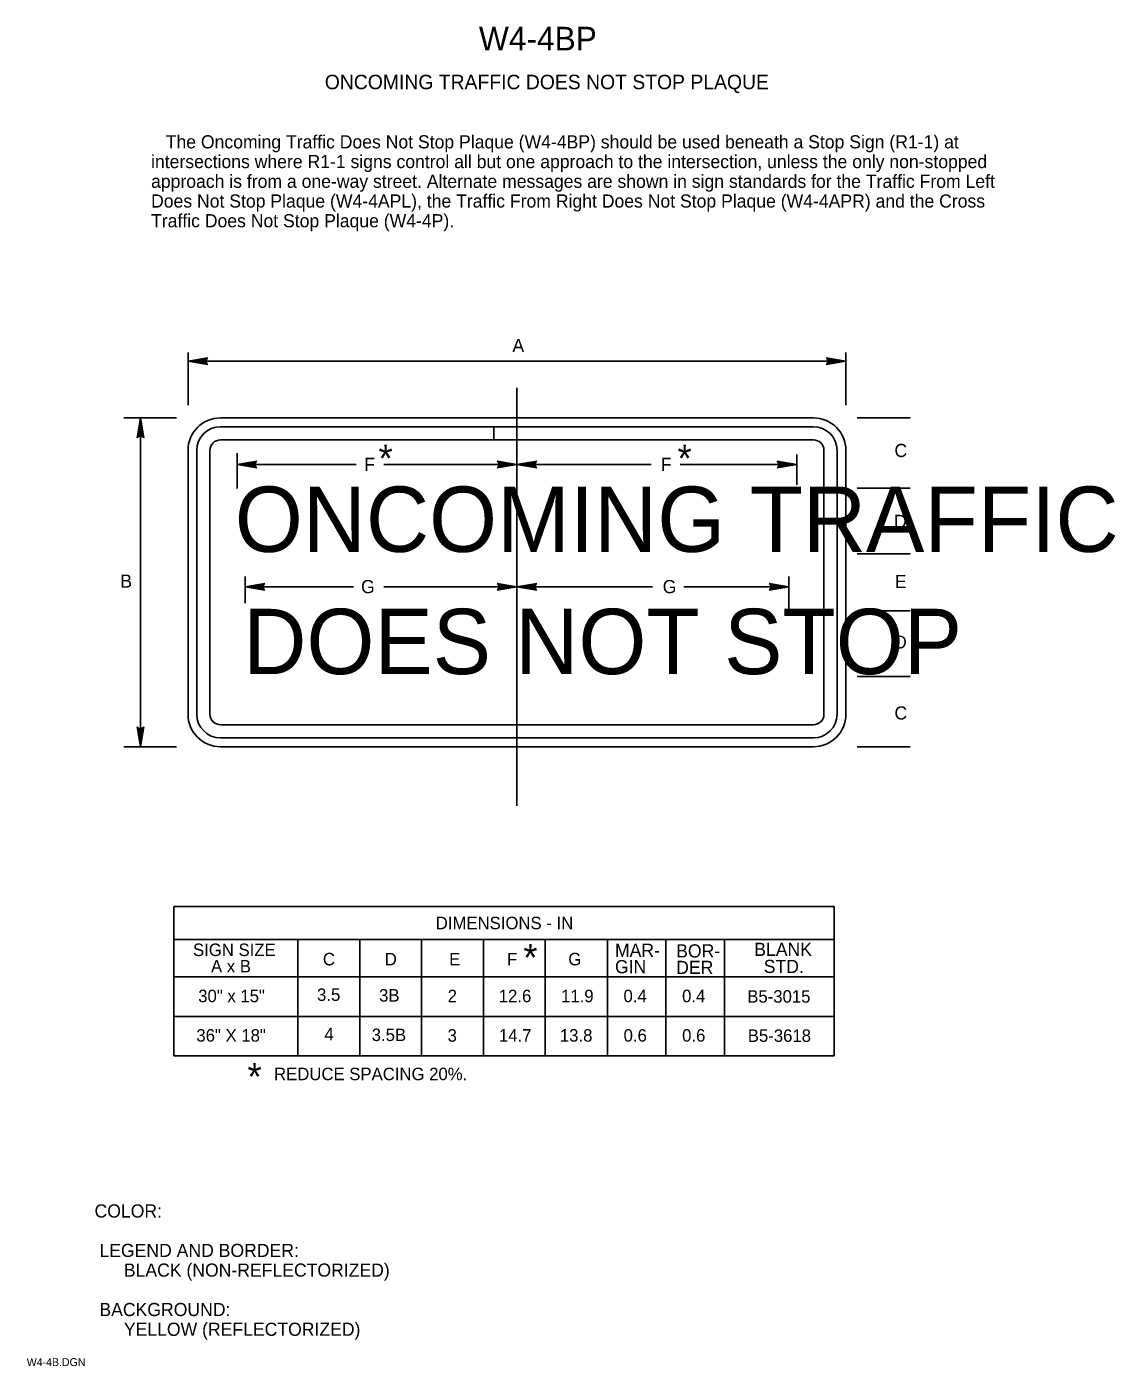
# Model space of a CAD drawing. Extents: x 0.013 to 0.219, y 0.004 to 0.259.
import ezdxf

# ---------------------------------------------------------------- set-up
doc = ezdxf.new("R2010")
doc.units = 0
for name, color, linetype in [('1', 7, 'Continuous'), ('2', 7, 'Continuous'), ('3', 7, 'Continuous')]:
    doc.layers.add(name, color=color, linetype=linetype)

# ---------------------------------------------------------------- blocks, each defined once
blk = doc.blocks.new('RARROW')
at = {"layer": '3'}
for p, q in [((-2.156, 0.285), (-2.2665, 0.384625)), ((-2.2665, 0.384625), (0, 0)), ((0, 0), (-2.2665, -0.379125)), ((-2.156, 0.285), (-2.075625, 0.12075)), ((0, 0), (-2.156, 0.285)), ((-2.14975, -0.2705), (0, 0)), ((-2.075625, 0.12075), (0, 0)), ((0, 0), (-2.074, -0.108)), ((-2.2665, -0.379125), (-2.14975, -0.2705)), ((-2.074, -0.108), (-2.14975, -0.2705))]:
    blk.add_line(p, q, dxfattribs=at)

msp = doc.modelspace()

# ---------------------------------------------------------------- linework, layer by layer
at = {"layer": '1'}
for p, q in [((0.10565, 0.11086), (0.10565, 0.19039)), ((0.0341, 0.12213), (0.0341, 0.18463)), ((0.10127, 0.18297), (0.04931, 0.18297)), ((0.10127, 0.18047), (0.10127, 0.18297)), ((0.16198, 0.18297), (0.10127, 0.18297)), ((0.10127, 0.18297), (0.10127, 0.18047)), ((0.04481, 0.17847), (0.04481, 0.1283)), ((0.04731, 0.1283), (0.04731, 0.17847)), ((0.04931, 0.18047), (0.10127, 0.18047)), ((0.10127, 0.18047), (0.16198, 0.18047)), ((0.16398, 0.17847), (0.16398, 0.1283)), ((0.16648, 0.1283), (0.16648, 0.17847)), ((0.05248, 0.17123), (0.05248, 0.17793)), ((0.10565, 0.17326), (0.10565, 0.17793)), ((0.15881, 0.17194), (0.15881, 0.17769)), ((0.05398, 0.14943), (0.05398, 0.15446)), ((0.10565, 0.15098), (0.10565, 0.1541)), ((0.15731, 0.14823), (0.15731, 0.15446)), ((0.16198, 0.1263), (0.04931, 0.1263)), ((0.04931, 0.1238), (0.16198, 0.1238))]:
    msp.add_line(p, q, dxfattribs=at)
for centre, radius, start, end in [((0.04931, 0.17847), 0.00617, 90, 180), ((0.16198, 0.17847), 0.00617, 360, 90), ((0.04931, 0.17847), 0.0045, 90, 180), ((0.16198, 0.17847), 0.0045, 0, 90), ((0.04931, 0.17847), 0.002, 90, 180), ((0.16198, 0.17847), 0.002, 0, 90), ((0.04931, 0.1283), 0.00617, 180, 270), ((0.04931, 0.1283), 0.0045, 180, 270), ((0.04931, 0.1283), 0.002, 180, 270), ((0.16198, 0.1283), 0.00617, 270, 0), ((0.16198, 0.1283), 0.0045, 270, 0), ((0.16198, 0.1283), 0.002, 270, 0)]:
    msp.add_arc(centre, radius, start, end, dxfattribs=at)
at = {"layer": '3'}
for p, q in [((0.04315, 0.18704), (0.04315, 0.1971)), ((0.16815, 0.18704), (0.16815, 0.1971)), ((0.16815, 0.19541), (0.04315, 0.19541)), ((0.04098, 0.18463), (0.03092, 0.18463)), ((0.04931, 0.18463), (0.16198, 0.18463)), ((0.17031, 0.18463), (0.18037, 0.18463)), ((0.04315, 0.17847), (0.04315, 0.1283)), ((0.16815, 0.17847), (0.16815, 0.1283)), ((0.07509, 0.17577), (0.05248, 0.17577)), ((0.10565, 0.17577), (0.08036, 0.17577)), ((0.10565, 0.17577), (0.13114, 0.17577)), ((0.13665, 0.17577), (0.15881, 0.17577)), ((0.17031, 0.1713), (0.18037, 0.1713)), ((0.17031, 0.1588), (0.18037, 0.1588)), ((0.07461, 0.15254), (0.05398, 0.15254)), ((0.10565, 0.15254), (0.08036, 0.15254)), ((0.10565, 0.15254), (0.13138, 0.15254)), ((0.13737, 0.15254), (0.15731, 0.15254)), ((0.17031, 0.14796), (0.18037, 0.14796)), ((0.17031, 0.13546), (0.18037, 0.13546)), ((0.04098, 0.12213), (0.03092, 0.12213)), ((0.04931, 0.12213), (0.16198, 0.12213)), ((0.17031, 0.12213), (0.18037, 0.12213)), ((0.04046, 0.09173), (0.16589, 0.09173)), ((0.04046, 0.09168), (0.04046, 0.06336)), ((0.16589, 0.09173), (0.16589, 0.06336)), ((0.16589, 0.08548), (0.04046, 0.08548)), ((0.06402, 0.08548), (0.06402, 0.06336)), ((0.07577, 0.08543), (0.07577, 0.06336)), ((0.08752, 0.08543), (0.08752, 0.06336)), ((0.09927, 0.08543), (0.09927, 0.06336)), ((0.11102, 0.08543), (0.11102, 0.06336)), ((0.12284, 0.08548), (0.12284, 0.06336)), ((0.13396, 0.08548), (0.13396, 0.06336)), ((0.14509, 0.08548), (0.14509, 0.06336)), ((0.04046, 0.07836), (0.16589, 0.07836)), ((0.04046, 0.07086), (0.16589, 0.07086)), ((0.04046, 0.06336), (0.16589, 0.06336))]:
    msp.add_line(p, q, dxfattribs=at)

# ---------------------------------------------------------------- block references
at = {"layer": '3', "xscale": 0.0016545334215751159}
for p, yscale, rotation in [((0.04315, 0.19541), -0.0016366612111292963, -180), ((0.0341, 0.18463), -0.0016366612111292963, 90), ((0.05248, 0.17577), -0.0016366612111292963, -180), ((0.10565, 0.17577), -0.0016366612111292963, -180), ((0.05398, 0.15254), -0.0016366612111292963, -180), ((0.10565, 0.15254), -0.0016366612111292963, -180), ((0.0341, 0.12213), 0.0016366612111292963, -90)]:
    msp.add_blockref('RARROW', p, dxfattribs=dict(at, yscale=yscale, rotation=rotation))
at = {"layer": '3', "xscale": 0.0016545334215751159, "yscale": 0.0016366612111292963}
for p in [(0.16815, 0.19541), (0.10565, 0.17577), (0.15881, 0.17577), (0.10565, 0.15254), (0.15731, 0.15254)]:
    msp.add_blockref('RARROW', p, dxfattribs=at)

# ---------------------------------------------------------------- texts
at = {"layer": '1'}
for s, height, p in [('W4-4BP', 0.0045, (0.09842, 0.2545)), ('ONCOMING TRAFFIC DOES NOT STOP PLAQUE', 0.0027503, (0.06913, 0.24713)), ('COLOR:', 0.0025, (0.02538, 0.03262)), (' LEGEND AND BORDER:', 0.0024998, (0.02538, 0.02512)), ('      BLACK (NON-REFLECTORIZED)', 0.0024998, (0.02538, 0.02138)), (' BACKGROUND:', 0.0024998, (0.02538, 0.01388)), ('      YELLOW (REFLECTORIZED)', 0.0024998, (0.02538, 0.01013)), ('W4-4B.DGN', 0.0015, (0.0125, 0.00438))]:
    msp.add_text(s, height=height, dxfattribs=at).set_placement(p)
at = {"layer": '2'}
for s, height, p in [('   The Oncoming Traffic Does Not Stop Plaque (W4-4BP) should be used beneath a Stop Sign (R1-1) at ', 0.0024998, (0.03612, 0.23588)), ('intersections where R1-1 signs control all but one approach to the intersection, unless the only non-stopped ', 0.00249975, (0.03612, 0.23213)), ('approach is from a one-way street. Alternate messages are shown in sign standards for the Traffic From Left ', 0.00249975, (0.03612, 0.22838)), ('Does Not Stop Plaque (W4-4APL), the Traffic From Right Does Not Stop Plaque (W4-4APR) and the Cross ', 0.0024998, (0.03612, 0.22463)), ('Traffic Does Not Stop Plaque (W4-4P).', 0.0024998, (0.03612, 0.22088))]:
    msp.add_text(s, height=height, dxfattribs=at).set_placement(p)
at = {"layer": '3'}
for s, height, p in [('A', 0.0025, (0.10479, 0.19716)), ('*', 0.00518, (0.13616, 0.17437)), ('C', 0.0025, (0.17738, 0.1772)), ('F', 0.0025, (0.13297, 0.17456)), ('ONCOMING TRAFFIC', 0.01242, (0.05204, 0.15917)), ('B', 0.0025, (0.03028, 0.15237)), ('G', 0.0025, (0.13334, 0.15132)), ('DOES NOT STOP', 0.01242, (0.05365, 0.13593)), ('DIMENSIONS - IN', 0.0023752, (0.09022, 0.08743)), ('SIGN SIZE', 0.002375, (0.04409, 0.08233)), ('MAR-', 0.0025, (0.12427, 0.08218)), ('BOR-', 0.0025, (0.1359, 0.08206)), ('BLANK', 0.0025, (0.15074, 0.08236)), ('A x B', 0.002375, (0.04751, 0.07921)), ('C', 0.00238, (0.06877, 0.08056)), ('D', 0.00238, (0.08052, 0.08056)), ('E', 0.00238, (0.09277, 0.08056)), ('F', 0.00238, (0.10377, 0.08056)), ('G', 0.00238, (0.1154, 0.08056)), ('GIN', 0.0025, (0.12427, 0.07906)), ('STD.', 0.0025, (0.15254, 0.07911)), ('DER', 0.0025, (0.1359, 0.07893)), ('30" x 15"', 0.002375, (0.04508, 0.07356)), ('3.5', 0.002375, (0.06766, 0.0738)), ('3B', 0.002375, (0.07945, 0.07367)), ('2', 0.00238, (0.09248, 0.07355)), ('12.6', 0.002375, (0.10219, 0.07356)), ('11.9', 0.002375, (0.11403, 0.07356)), ('0.4', 0.002375, (0.12589, 0.07356)), ('0.4', 0.002375, (0.13702, 0.07356)), ('B5-3015', 0.002375, (0.14941, 0.07347)), ('36" X 18"', 0.002375, (0.04473, 0.06606)), ('4', 0.00238, (0.06905, 0.0663)), ('3.5B', 0.002375, (0.07805, 0.06617)), ('3', 0.00238, (0.09247, 0.06605)), ('14.7', 0.002375, (0.10222, 0.06606)), ('13.8', 0.002375, (0.1138, 0.06606)), ('0.6', 0.002375, (0.12591, 0.06606)), ('0.6', 0.002375, (0.13703, 0.06606)), ('B5-3618', 0.002375, (0.14951, 0.06601)), ('REDUCE SPACING 20%.', 0.0023752, (0.05949, 0.05873))]:
    msp.add_text(s, height=height, dxfattribs=at).set_placement(p)
for s, height, p in [('*', 0.00518, (0.07934, 0.17437)), ('F', 0.0025, (0.07661, 0.17456)), ('D', 0.0025, (0.1773, 0.16372)), ('G', 0.0025, (0.07602, 0.15132)), ('E', 0.0025, (0.17744, 0.15228)), ('D', 0.0025, (0.1773, 0.14078)), ('C', 0.0025, (0.17738, 0.1273)), ('*', 0.00518, (0.10685, 0.07946)), ('*', 0.00518, (0.05444, 0.05682))]:
    msp.add_text(s, height=height, rotation=360, dxfattribs=at).set_placement(p)

doc.saveas('drawing.dxf')
